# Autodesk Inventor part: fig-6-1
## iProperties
Created: 2004-05
Part Number: fig-6-1
Document SubType Name: Modeling
Designer: CADCIM Technologies
Manufacturer: Standard
Standards Organization: Custom
Density: 1 g/cm^3
Author: CADCIM Technologies
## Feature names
1. Extrusion1
2. Hole1
3. Circular Pattern1
